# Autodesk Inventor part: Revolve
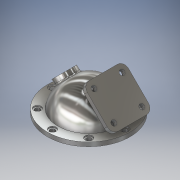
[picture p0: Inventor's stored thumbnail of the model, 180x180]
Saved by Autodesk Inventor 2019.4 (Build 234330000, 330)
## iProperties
Created: 2019-04
Part Number: Revolve
Material: Nickel-Copper Alloy 400
Document SubType Name: Modeling
Designer: Synergysoft
Density: 8.83 g/cm^3
Appearance: Chrome - Polished
Author: Synergysoft
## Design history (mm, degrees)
sketch "Sketch1"
  geometry: L1 (6.5, 50)-(1.5, 50); L2 (0, 0)-(43.724, 0); L3 (1.5, 50)-(1.5, 34.968); L4 (0, 35)-(0, 32); L5 (6.5, 50)-(6.5, 37.44); L6 (38, 0)-(32, 0); A1 r 32 centre (0, 0) between (32, 0) and (0, 32); A2 r 38 centre (0, 0) between (38, 0) and (6.5, 37.44); A3 r 35 centre (0, 0) between (1.5, 34.968) and (0, 35); 1 further point
  constraints: 12 end point, 6 point on circle, 4 coincident, 3 centre point, 3 point on line, 2 parallel, 1 collinear, 1 horizontal, 1 vertical
  dimensions: "d0" = 64 diameter of A1; "d2" = 38 radius of A2; "d8" = 5 distance of L1.start L1.end; "d9" = 1.5 distance from line of point (0, 0) L3; "d10" = 35 radius of A3; "d11" = 50 distance between parallel lines of L2 L1
revolve "Revolution1" sketch "Sketch1" stored, may be unused: angle "d12" = 90 deg
sketch "Sketch2"
  geometry: L1 (0, 0)-(35.355, 35.355); L2 (32, 0)-(-32, 0) reference; L3 (14.142, 49.497)-(17.678, 53.033); L4 (17.678, 53.033)-(53.033, 17.678); L5 (53.033, 17.678)-(49.497, 14.142); L6 (49.497, 14.142)-(14.142, 49.497); L7 (14.142, 49.497)-(53.033, 17.678); L8 (17.678, 53.033)-(49.497, 14.142); L9 (0, 0)-(-29.698, 29.698); 1 further point
  constraints: 16 end point, 3 midpoint, 2 parallel, 2 perpendicular
  dimensions: "d13" = 50 distance of L1.end L1.start; "d14" = 45 deg angle of L2 L1; "d15" = 5 distance of L3.start L3.end; "d16" = 50 distance of L3.end L4.end; "d22" = 42 distance of L9.end L1.start; "d23" = 45 deg angle of L2 L9
extrude "Extrusion1" join sketch "Sketch2" stored distance "d17" = 50; taper "d18" = 0 deg
sketch "Sketch3"
  geometry: C1 r 16 at (-25, 25); 1 further point
  constraints: 1 centre point, 1 coincident
  dimensions: "d19" = 32 diameter of C1
extrude "Extrusion2" join sketch "Sketch3" stored distance "d20" = 50; taper "d21" = 0 deg
workplane "Work Plane1"
sketch "Sketch4"
  geometry: C1 r 12.5 at (0, 0); 1 further point
  constraints: 1 centre point, 1 coincident
  dimensions: "d26" = 25 diameter of C1
extrude "Extrusion3" join sketch "Sketch4" stored distance "d27" = 50; taper "d28" = 0 deg
sketch "Sketch5"
  geometry: C1 r 12.5 at (0, 0) reference; 2 further points
  constraints: 1 coincident
hole "Hole1" sketch "Sketch5" at (0, 0) diameter "d29" = 14; stored, may be unused: countersink angle "d33" = 90 deg, drill point angle "d35" = 118 deg; dims "d30" = 6, "d31" = 4, "d32" = 2, "d34" = 8
fillet "Fillet1" dims "d36" = 8
sketch "Sketch6"
  geometry: A1 r 8 centre (42, 34) between (50, 34) and (42, 42) reference; A2 r 8 centre (42, 0) between (42, -8) and (50, 0) reference; A3 r 8 centre (8, 0) between (0, 0) and (8, -8) reference; A4 r 8 centre (8, 34) between (8, 42) and (0, 34) reference; 5 further points
  constraints: 4 coincident
hole "Hole2" sketch "Sketch6" at (42, 34), (42, 0), (8, 0), (8, 34) diameter "d37" = 6; stored, may be unused: countersink angle "d41" = 90 deg, drill point angle "d43" = 118 deg; dims "d38" = 6, "d39" = 4, "d40" = 2, "d42" = 8
sketch "Sketch7"
  geometry: 1 further point
fillet "Fillet2" dims "d44" = 2
sketch "Sketch8"
  geometry: 2 further points
  constraints: 1 horizontal alignment
  dimensions: "d45" = 44 distance of point (0, 0) point (-44, 0)
hole "Hole3" sketch "Sketch8" at (-44, 0) diameter "d46" = 6; stored, may be unused: countersink angle "d50" = 90 deg, drill point angle "d52" = 118 deg; dims "d47" = 6, "d48" = 9, "d49" = 1.5, "d51" = 8
pattern_circular "Circular Pattern1" dims angle "d54" = 360 deg
sketch "Sketch9"
  geometry: C1 r 16 at (0, 0); C2 r 7 at (0, 0) reference; 1 further point
  constraints: 1 centre point, 1 coincident
  dimensions: "d56" = 32 diameter of C1
extrude "Extrusion4" join sketch "Sketch9" distance "d57" = 3; taper "d58" = 0 deg
chamfer "Chamfer1" distance "d59" = 1.5; stored, may be unused: second distance "d60" = 2, angle "d61" = 45 deg
body "Solid1"
other parameters: "d6" = 1.5, "d25" = 25
